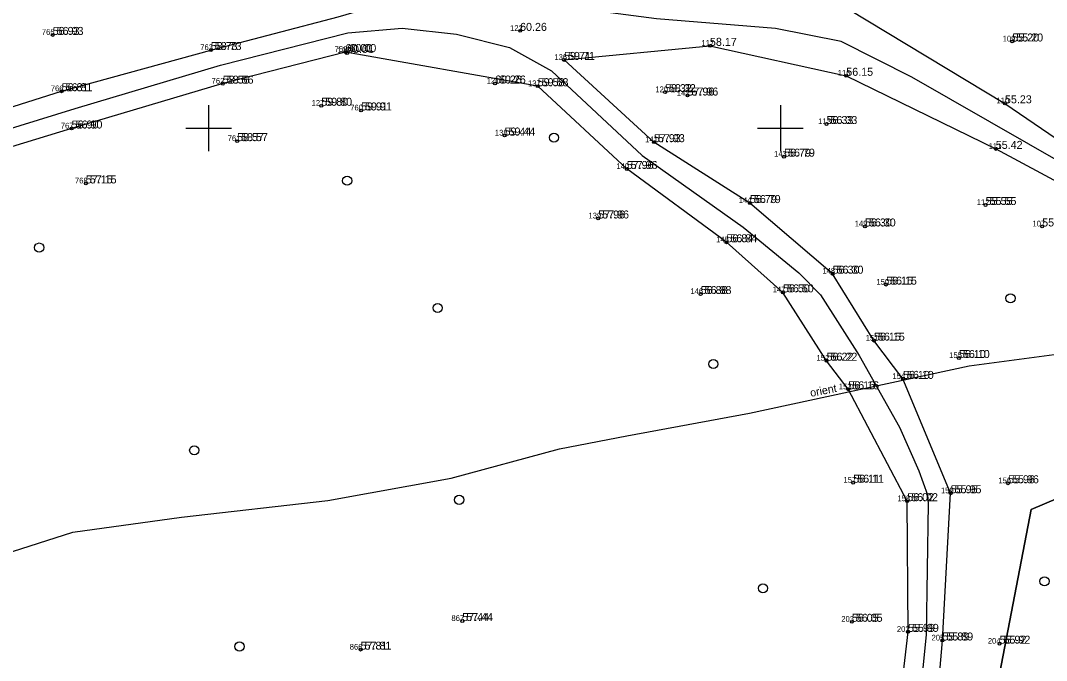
# Model space of a CAD drawing. Extents: x 554846 to 556995, y 6445875 to 6446723.
# Drawn here: x 555383.6 to 555473.3, y 6446153.5 to 6446209.4 of the extents above; entities that cross this region are included whole.
import ezdxf

# ---------------------------------------------------------------- set-up
doc = ezdxf.new("R2010")
doc.units = 0
for name, color, linetype in [('HALJASTUS', 7, 'Continuous'), ('KORGUS-EH2000', 7, 'Continuous'), ('MOOTKORG-EH2000', 7, 'Continuous'), ('MOOTMPUNKT', 7, 'Continuous'), ('MOOTNR', 7, 'Continuous'), ('PIIR', 7, 'Continuous'), ('SITRASS', 7, 'Continuous'), ('TEE', 7, 'Continuous'), ('VORK', 7, 'Continuous')]:
    doc.layers.add(name, color=color, linetype=linetype)

msp = doc.modelspace()

# ---------------------------------------------------------------- linework, layer by layer
at = {"layer": 'HALJASTUS'}
for centre in [(555430.2, 6446199.178), (555412.117, 6446195.408), (555385.179, 6446189.566), (555470.123, 6446185.136), (555420.028, 6446184.288), (555444.14, 6446179.388), (555398.742, 6446171.849), (555421.912, 6446167.514), (555448.472, 6446159.786), (555473.09, 6446160.399), (555402.698, 6446154.697)]:
    msp.add_circle(centre, 0.4, dxfattribs=at)
at = {"layer": 'KORGUS-EH2000'}
for centre in [(555386.365, 6446208.152), (555470.281, 6446207.578), (555400.189, 6446206.83), (555411.969, 6446206.659), (555431.081, 6446205.966), (555387.148, 6446203.23), (555401.236, 6446203.893), (555425.04, 6446203.904), (555428.776, 6446203.669), (555439.909, 6446203.147), (555441.874, 6446202.853), (555409.854, 6446201.96), (555413.328, 6446201.552), (555388.023, 6446199.971), (555454.032, 6446200.363), (555402.491, 6446198.869), (555425.881, 6446199.36), (555438.945, 6446198.778), (555450.322, 6446197.511), (555436.561, 6446196.434), (555389.262, 6446195.173), (555447.334, 6446193.455), (555467.947, 6446193.287), (555434.069, 6446192.109), (555457.392, 6446191.409), (555472.891, 6446191.411), (555445.278, 6446190.027), (555454.567, 6446187.282), (555459.242, 6446186.325), (555443.027, 6446185.504), (555450.224, 6446185.653), (555458.182, 6446181.43), (555465.611, 6446179.911), (555454.036, 6446179.674), (555460.718, 6446178.087), (555455.935, 6446177.178), (555456.367, 6446169.011), (555464.888, 6446168.091), (555469.908, 6446168.965), (555461.088, 6446167.397), (555422.182, 6446156.925), (555456.247, 6446156.857), (555461.161, 6446155.974), (555464.165, 6446155.222), (555469.162, 6446154.94), (555413.29, 6446154.422)]:
    msp.add_circle(centre, 0.125, dxfattribs=at)
at = {"layer": 'MOOTMPUNKT'}
for centre in [(555427.238, 6446208.505), (555386.365, 6446208.152), (555470.281, 6446207.578), (555400.189, 6446206.83), (555411.969, 6446206.659), (555443.842, 6446207.197), (555412.107, 6446206.568), (555431.081, 6446205.966), (555455.762, 6446204.58), (555387.148, 6446203.23), (555401.236, 6446203.893), (555425.04, 6446203.904), (555428.776, 6446203.669), (555439.909, 6446203.147), (555441.874, 6446202.853), (555469.637, 6446202.173), (555409.854, 6446201.96), (555413.328, 6446201.552), (555388.023, 6446199.971), (555454.032, 6446200.363), (555402.491, 6446198.869), (555425.881, 6446199.36), (555438.945, 6446198.778), (555468.833, 6446198.189), (555450.322, 6446197.511), (555436.561, 6446196.434), (555389.262, 6446195.173), (555447.334, 6446193.455), (555467.947, 6446193.287), (555434.069, 6446192.109), (555457.392, 6446191.409), (555472.891, 6446191.411), (555445.278, 6446190.027), (555454.567, 6446187.282), (555459.242, 6446186.325), (555443.027, 6446185.504), (555450.224, 6446185.653), (555458.182, 6446181.43), (555465.611, 6446179.911), (555454.036, 6446179.674), (555460.718, 6446178.087), (555455.935, 6446177.178), (555456.367, 6446169.011), (555464.888, 6446168.091), (555469.908, 6446168.965), (555461.088, 6446167.397), (555422.182, 6446156.925), (555456.247, 6446156.857), (555461.161, 6446155.974), (555464.165, 6446155.222), (555469.162, 6446154.94), (555413.29, 6446154.422)]:
    msp.add_circle(centre, 0.125, dxfattribs=at)
at = {"layer": 'PIIR'}
msp.add_lwpolyline([(555848.15, 6446270.05), (555770.44, 6446257.1), (555601.76, 6446236.19), (555592.08, 6446205.8), (555590.17, 6446199.81), (555547.72, 6446198.88), (555471.93, 6446166.68), (555437.75, 6445988.89), (555430.84, 6445989.84), (555424.9, 6445990.66), (555394.94, 6445995.15), (555348.46, 6446002.11), (555303.97, 6446008.78), (555290.27, 6445950.91), (555289.66, 6445948.39), (555259.76, 6445985.47)], dxfattribs=at)
msp.add_lwpolyline([(555594.35, 6446199.31), (555580.72, 6446194.53), (555573.2, 6446192.45), (555562.73, 6446139.8), (555499.33, 6446154.09), (555491.55, 6446119.62), (555486.57, 6446097.52), (555481.82, 6446076.44), (555475.25, 6446047.27), (555464.73, 6446000.58), (555471.74, 6445999.08), (555467.38, 6445984.82), (555437.75, 6445988.89), (555471.93, 6446166.68), (555547.72, 6446198.88), (555590.17, 6446199.81)], close=True, dxfattribs=at)
at = {"layer": 'SITRASS'}
msp.add_lwpolyline([(555305.763, 6446088.513), (555311.729, 6446098.729), (555315.174, 6446103.591), (555318.557, 6446109.253), (555319.725, 6446114.115), (555320.34, 6446119.408), (555319.91, 6446123.531), (555321.017, 6446127.039), (555334.918, 6446144.825), (555339.434, 6446148.129), (555341.895, 6446149.324), (555360.137, 6446155.971), (555367.799, 6446158.187), (555388.114, 6446164.693), (555397.639, 6446165.994), (555410.433, 6446167.471), (555421.224, 6446169.405), (555430.679, 6446171.973), (555436.583, 6446173.098), (555447.304, 6446175.102), (555466.494, 6446179.217), (555474.824, 6446180.342)], dxfattribs=at)
at = {"layer": 'TEE'}
for points in [[(555377.982, 6446233.661), (555385.778, 6446233.467), (555395.46, 6446230.347), (555405.87, 6446224.702), (555409.386, 6446222.845), (555420.953, 6446215.507), (555426.678, 6446214.289), (555441.901, 6446211.558), (555455.955, 6446210.414), (555469.637, 6446202.173), (555476.682, 6446197.344)], [(555475.136, 6446196.652), (555461.497, 6446204.471), (555455.311, 6446207.569), (555449.584, 6446208.728), (555439.165, 6446209.561), (555427.759, 6446211.043), (555420.126, 6446213.794), (555407.523, 6446222.088), (555402.096, 6446224.984), (555394.437, 6446228.805), (555386.933, 6446231.369), (555384.183, 6446231.72), (555378.357, 6446231.933)], [(555375.151, 6446199.451), (555387.148, 6446203.23), (555400.189, 6446206.83), (555411.335, 6446209.731), (555418.226, 6446211.78), (555417.749, 6446213.004)], [(555376.703, 6446198.148), (555388.324, 6446201.726), (555401.027, 6446205.513), (555412.181, 6446208.343), (555416.933, 6446208.736), (555421.672, 6446208.209), (555426.3, 6446207.063), (555429.993, 6446205.008), (555437.916, 6446197.623), (555446.737, 6446191.339), (555451.603, 6446187.366), (555453.505, 6446185.442), (555456.897, 6446180.124), (555460.406, 6446173.862), (555462.096, 6446170.051), (555462.87, 6446167.967), (555462.93, 6446167.164), (555462.761, 6446155.758), (555461.011, 6446138.135)], [(555455.467, 6446096.135), (555457.379, 6446102.627), (555458.705, 6446112.603), (555461.978, 6446127.235), (555462.692, 6446137.947), (555464.165, 6446155.222), (555464.888, 6446168.091), (555460.718, 6446178.087), (555458.182, 6446181.43), (555454.567, 6446187.282), (555447.334, 6446193.455), (555438.945, 6446198.778), (555431.081, 6446205.966), (555443.842, 6446207.197), (555455.762, 6446204.58), (555468.833, 6446198.189), (555475.066, 6446194.836)], [(555449.194, 6446092.47), (555452.214, 6446097.567), (555454.113, 6446103.09), (555455.792, 6446113.469), (555458.286, 6446127.259), (555459.068, 6446137.953), (555461.161, 6446155.974), (555461.088, 6446167.397), (555455.935, 6446177.178), (555454.036, 6446179.674), (555450.224, 6446185.653), (555445.278, 6446190.027), (555436.561, 6446196.434), (555428.776, 6446203.669), (555411.969, 6446206.659), (555401.236, 6446203.893), (555388.023, 6446199.971), (555376.051, 6446196.325)]]:
    msp.add_lwpolyline(points, dxfattribs=at)
at = {"layer": 'VORK'}
for p, q in [((555400, 6446202), (555400, 6446198)), ((555450, 6446202), (555450, 6446198)), ((555398, 6446200), (555402, 6446200)), ((555448, 6446200), (555452, 6446200))]:
    msp.add_line(p, q, dxfattribs=at)

# ---------------------------------------------------------------- texts
at = {"layer": 'KORGUS-EH2000'}
for s, p in [('56.93', (555386.715, 6446208.152)), ('55.20', (555470.631, 6446207.578)), ('58.73', (555400.539, 6446206.83)), ('60.00', (555412.319, 6446206.659)), ('59.71', (555431.431, 6446205.966)), ('58.56', (555401.586, 6446203.893)), ('60.26', (555425.39, 6446203.904)), ('59.58', (555429.126, 6446203.669)), ('56.81', (555387.498, 6446203.23)), ('58.32', (555440.259, 6446203.147)), ('57.96', (555442.224, 6446202.853)), ('59.80', (555410.204, 6446201.96)), ('59.91', (555413.678, 6446201.552)), ('56.90', (555388.373, 6446199.971)), ('56.33', (555454.382, 6446200.363)), ('59.44', (555426.231, 6446199.36)), ('58.57', (555402.841, 6446198.869)), ('57.93', (555439.295, 6446198.778)), ('56.79', (555450.672, 6446197.511)), ('57.96', (555436.911, 6446196.434)), ('57.15', (555389.612, 6446195.173)), ('56.79', (555447.684, 6446193.455)), ('55.55', (555468.297, 6446193.287)), ('57.96', (555434.419, 6446192.109)), ('56.30', (555457.742, 6446191.409)), ('56.84', (555445.628, 6446190.027)), ('56.30', (555454.917, 6446187.282)), ('56.88', (555443.377, 6446185.504)), ('56.50', (555450.574, 6446185.653)), ('56.15', (555459.592, 6446186.325)), ('56.15', (555458.532, 6446181.43)), ('56.22', (555454.386, 6446179.674)), ('56.10', (555465.961, 6446179.911)), ('56.10', (555461.068, 6446178.087)), ('56.16', (555456.285, 6446177.178)), ('56.11', (555456.717, 6446169.011)), ('55.96', (555470.258, 6446168.965)), ('55.95', (555465.238, 6446168.091)), ('56.02', (555461.438, 6446167.397)), ('57.44', (555422.532, 6446156.925)), ('56.05', (555456.597, 6446156.857)), ('55.99', (555461.511, 6446155.974)), ('55.89', (555464.515, 6446155.222)), ('55.92', (555469.512, 6446154.94)), ('57.81', (555413.64, 6446154.422))]:
    msp.add_text(s, height=0.7, dxfattribs=at).set_placement(p)
at = {"layer": 'MOOTKORG-EH2000'}
for s, p in [('56.93', (555386.365, 6446208.152)), ('60.26', (555427.238, 6446208.505)), ('58.17', (555443.842, 6446207.197)), ('55.20', (555470.281, 6446207.578)), ('58.73', (555400.189, 6446206.83)), ('60.00', (555411.969, 6446206.659)), ('60.01', (555412.107, 6446206.568)), ('59.71', (555431.081, 6446205.966)), ('56.15', (555455.762, 6446204.58)), ('58.56', (555401.236, 6446203.893)), ('60.26', (555425.04, 6446203.904)), ('59.58', (555428.776, 6446203.669)), ('56.81', (555387.148, 6446203.23)), ('58.32', (555439.909, 6446203.147)), ('57.96', (555441.874, 6446202.853)), ('59.80', (555409.854, 6446201.96)), ('55.23', (555469.637, 6446202.173)), ('59.91', (555413.328, 6446201.552)), ('56.90', (555388.023, 6446199.971)), ('56.33', (555454.032, 6446200.363)), ('59.44', (555425.881, 6446199.36)), ('58.57', (555402.491, 6446198.869)), ('57.93', (555438.945, 6446198.778)), ('55.42', (555468.833, 6446198.189)), ('56.79', (555450.322, 6446197.511)), ('57.96', (555436.561, 6446196.434)), ('57.15', (555389.262, 6446195.173)), ('56.79', (555447.334, 6446193.455)), ('55.55', (555467.947, 6446193.287)), ('57.96', (555434.069, 6446192.109)), ('56.30', (555457.392, 6446191.409)), ('55.40', (555472.891, 6446191.411)), ('56.84', (555445.278, 6446190.027)), ('56.30', (555454.567, 6446187.282)), ('56.88', (555443.027, 6446185.504)), ('56.50', (555450.224, 6446185.653)), ('56.15', (555459.242, 6446186.325)), ('56.15', (555458.182, 6446181.43)), ('56.22', (555454.036, 6446179.674)), ('56.10', (555465.611, 6446179.911)), ('56.10', (555460.718, 6446178.087)), ('56.16', (555455.935, 6446177.178)), ('56.11', (555456.367, 6446169.011)), ('55.96', (555469.908, 6446168.965)), ('55.95', (555464.888, 6446168.091)), ('56.02', (555461.088, 6446167.397)), ('57.44', (555422.182, 6446156.925)), ('56.05', (555456.247, 6446156.857)), ('55.99', (555461.161, 6446155.974)), ('55.89', (555464.165, 6446155.222)), ('55.92', (555469.162, 6446154.94)), ('57.81', (555413.29, 6446154.422))]:
    msp.add_text(s, height=0.7, dxfattribs=at).set_placement(p)
at = {"layer": 'MOOTNR'}
for s, p in [('765', (555385.415, 6446208.152)), ('122', (555426.363, 6446208.505)), ('117', (555443.092, 6446207.197)), ('109', (555469.431, 6446207.578)), ('763', (555399.264, 6446206.83)), ('759', (555411.019, 6446206.659)), ('126', (555411.257, 6446206.568)), ('136', (555430.231, 6446205.966)), ('116', (555455.012, 6446204.58)), ('762', (555400.261, 6446203.893)), ('121', (555424.315, 6446203.904)), ('137', (555427.926, 6446203.669)), ('766', (555386.198, 6446203.23)), ('120', (555439.059, 6446203.147)), ('142', (555440.949, 6446202.853)), ('127', (555409.004, 6446201.96)), ('110', (555468.887, 6446202.173)), ('760', (555412.378, 6446201.552)), ('113', (555453.307, 6446200.363)), ('767', (555387.073, 6446199.971)), ('138', (555425.031, 6446199.36)), ('761', (555401.666, 6446198.869)), ('141', (555438.17, 6446198.778)), ('143', (555449.447, 6446197.511)), ('111', (555468.208, 6446198.189)), ('140', (555435.661, 6446196.434)), ('768', (555388.312, 6446195.173)), ('144', (555446.359, 6446193.455)), ('112', (555467.172, 6446193.287)), ('139', (555433.219, 6446192.109)), ('149', (555456.492, 6446191.409)), ('107', (555472.041, 6446191.411)), ('145', (555444.378, 6446190.027)), ('148', (555453.667, 6446187.282)), ('147', (555449.324, 6446185.653)), ('150', (555458.392, 6446186.325)), ('146', (555442.127, 6446185.504)), ('151', (555457.457, 6446181.43)), ('152', (555453.161, 6446179.674)), ('155', (555464.761, 6446179.911)), ('154', (555459.793, 6446178.087)), ('153', (555455.11, 6446177.178)), ('157', (555455.517, 6446169.011)), ('156', (555469.058, 6446168.965)), ('159', (555464.038, 6446168.091)), ('158', (555460.238, 6446167.397)), ('867', (555421.232, 6446156.925)), ('203', (555455.322, 6446156.857)), ('202', (555460.186, 6446155.974)), ('205', (555463.215, 6446155.222)), ('866', (555412.34, 6446154.422)), ('204', (555468.137, 6446154.94))]:
    msp.add_text(s, height=0.5, dxfattribs=at).set_placement(p)
at = {"layer": 'SITRASS'}
msp.add_text('orient', height=0.7, rotation=11.03956, dxfattribs=at).set_placement((555452.669, 6446176.51))

doc.saveas('drawing.dxf')
